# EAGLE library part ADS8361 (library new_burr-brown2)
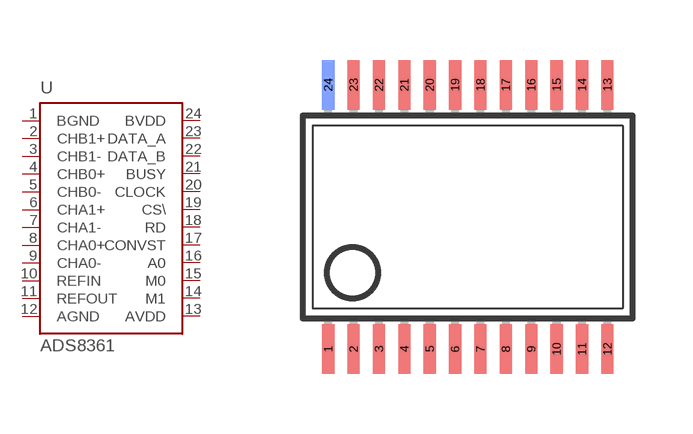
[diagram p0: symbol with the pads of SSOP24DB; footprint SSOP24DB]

Designator prefix -

## ADS8361  [SSOP24DB]
1  BGND  in
2  CHB1+  in
3  CHB1-  in
4  CHB0+  in
5  CHB0-  in
6  CHA1+  in
7  CHA1-  in
8  CHA0+  in
9  CHA0-  in
10  REFIN  in
11  REFOUT  in
12  AGND  in
13  AVDD  pwr
14  M1  pwr
15  M0  out
16  A0  out
17  CONVST  out
18  RD  in
19  CS\  in
20  CLOCK  in
21  BUSY  in
22  DATA_B  pwr
23  DATA_A  pwr
24  BVDD  pwr

## Footprint SSOP24DB (pad centres in mm)
smd 0.305 x 1.245: 1 -2.223,-3.302; 2 -1.587,-3.302; 3 -0.953,-3.302; 4 -0.318,-3.302; 5 0.318,-3.302; 6 0.953,-3.302; 7 1.587,-3.302; 8 2.223,-3.302; 9 2.857,-3.302; 10 3.493,-3.302; 11 4.128,-3.302; 12 4.763,-3.302; 13 4.763,3.302; 14 4.128,3.302; 15 3.493,3.302; 16 2.857,3.302; 17 2.223,3.302; 18 1.587,3.302; 19 0.953,3.302; 20 0.318,3.302; 21 -0.318,3.302; 22 -0.953,3.302; 23 -1.587,3.302
smd 0.305 x 1.245 bottom: 24 -2.223,3.302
